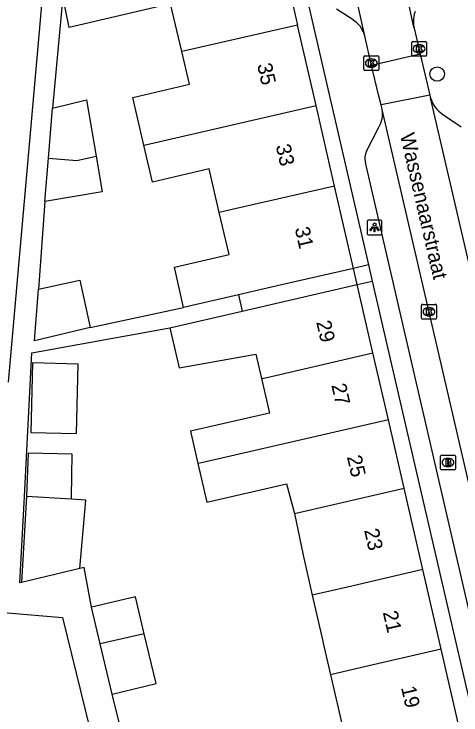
# Model space of a CAD drawing. Extents: x 160861 to 161308, y 384024 to 384878.
# Drawn here: x 160956.66 to 160986.91, y 384771.23 to 384818.67 of the extents above; entities that cross this region are included whole.
import ezdxf

# ---------------------------------------------------------------- set-up
doc = ezdxf.new("R2010")
doc.units = 0
for name, color, linetype in [('IMGEO_Boom', 7, 'Continuous'), ('IMGEO_Brandkraan', 7, 'Continuous'), ('IMGEO_Kolk', 7, 'Continuous'), ('IMGEO_Lichtpunt', 7, 'Continuous'), ('IMGEO_Openbare_ruimte_label', 7, 'Continuous'), ('IMGEO_Pand', 7, 'Continuous'), ('IMGEO_Pand_nummerreeks', 7, 'Continuous'), ('IMGEO_Pand_overbouw', 7, 'Continuous'), ('IMGEO_Rijbaan_lokaal_open', 7, 'Continuous'), ('IMGEO_Voetpad_open', 7, 'Continuous')]:
    doc.layers.add(name, color=color, linetype=linetype)

msp = doc.modelspace()

# ---------------------------------------------------------------- linework, layer by layer
at = {"layer": 'IMGEO_Boom'}
msp.add_circle((160985.295, 384814.604), 0.489, dxfattribs=at)
at = {"layer": 'IMGEO_Brandkraan'}
for p, q in [((160985.526, 384787.894), (160985.526, 384788.746)), ((160985.601, 384788.82), (160986.453, 384788.82)), ((160986.014, 384788.6), (160986.039, 384788.6)), ((160986.527, 384788.746), (160986.527, 384787.894)), ((160986.037, 384788.04), (160986.012, 384788.04)), ((160986.453, 384787.82), (160985.601, 384787.82))]:
    msp.add_line(p, q, dxfattribs=at)
for points in [[(160985.526, 384787.894), (160985.526, 384788.746)], [(160985.601, 384788.82), (160986.453, 384788.82)], [(160985.874, 384788.52), (160985.874, 384788.12), (160986.087, 384788.12)], [(160986.105, 384788.52), (160985.874, 384788.52)], [(160986.053, 384788.439), (160985.999, 384788.439), (160985.999, 384788.363)], [(160986.527, 384788.746), (160986.527, 384787.894)], [(160985.999, 384788.363), (160986.052, 384788.363)], [(160986.061, 384788.287), (160985.999, 384788.287), (160985.999, 384788.206)], [(160985.999, 384788.206), (160986.061, 384788.206)], [(160986.453, 384787.82), (160985.601, 384787.82)]]:
    msp.add_lwpolyline(points, dxfattribs=at)
for centre, radius, start, end in [((160985.603, 384788.744), 0.0765, 91.552, 178.448), ((160985.603, 384788.744), 0.0765, 91.552, 178.448), ((160986.054, 384788.401), 0.0379, 267.8285, 90.9355), ((160986.109, 384788.375), 0.145, 59.4692, 91.5367), ((160986.134, 384788.422), 0.0922, 285.5137, 58.1501), ((160986.451, 384788.744), 0.0765, 1.552, 88.448), ((160986.451, 384788.744), 0.0765, 1.552, 88.448), ((160986.062, 384788.246), 0.0404, 269.8759, 90.5077), ((160986.093, 384788.371), 0.251, 268.6676, 293.5347), ((160986.139, 384788.23), 0.105, 301.3115, 78.989), ((160985.603, 384787.896), 0.0765, 181.552, 268.448), ((160985.603, 384787.896), 0.0765, 181.552, 268.448), ((160986.451, 384787.896), 0.0765, 271.552, 358.448), ((160986.451, 384787.896), 0.0765, 271.552, 358.448)]:
    msp.add_arc(centre, radius, start, end, dxfattribs=at)
for centre, major_axis, ratio, start_param, end_param in [((160986.013, 384788.32), (-0.387, 0.002), 0.722429, 4.712389, 7.853982), ((160986.038, 384788.32), (-0.39, 0.002), 0.717154, 1.570796, 4.712389)]:
    msp.add_ellipse(centre, major_axis=major_axis, ratio=ratio, start_param=start_param, end_param=end_param, dxfattribs=at)
at = {"layer": 'IMGEO_Kolk'}
for p, q in [((160983.572, 384815.895), (160983.572, 384816.747)), ((160983.647, 384816.821), (160984.499, 384816.821)), ((160984.06, 384816.601), (160984.085, 384816.601)), ((160984.573, 384816.747), (160984.573, 384815.895)), ((160984.083, 384816.041), (160984.058, 384816.041)), ((160980.337, 384814.922), (160980.337, 384815.774)), ((160980.412, 384815.848), (160981.264, 384815.848)), ((160980.825, 384815.628), (160980.85, 384815.628)), ((160981.338, 384815.774), (160981.338, 384814.922)), ((160984.499, 384815.821), (160983.647, 384815.821)), ((160980.848, 384815.068), (160980.823, 384815.068)), ((160981.264, 384814.848), (160980.412, 384814.848)), ((160984.242, 384798.095), (160984.242, 384798.947)), ((160984.317, 384799.021), (160985.169, 384799.021)), ((160985.243, 384798.947), (160985.243, 384798.095)), ((160984.73, 384798.801), (160984.755, 384798.801)), ((160985.169, 384798.021), (160984.317, 384798.021)), ((160984.753, 384798.241), (160984.728, 384798.241))]:
    msp.add_line(p, q, dxfattribs=at)
for points in [[(160983.572, 384815.895), (160983.572, 384816.747)], [(160983.647, 384816.821), (160984.499, 384816.821)], [(160983.893, 384816.521), (160984.016, 384816.521), (160984.016, 384816.37), (160984.146, 384816.521), (160984.31, 384816.521), (160984.164, 384816.37), (160984.317, 384816.121), (160984.165, 384816.121), (160984.08, 384816.285), (160984.016, 384816.218), (160984.016, 384816.121), (160983.893, 384816.121), (160983.893, 384816.521)], [(160984.573, 384816.747), (160984.573, 384815.895)], [(160980.337, 384814.922), (160980.337, 384815.774)], [(160980.412, 384815.848), (160981.264, 384815.848)], [(160980.658, 384815.548), (160980.781, 384815.548), (160980.781, 384815.397), (160980.911, 384815.548), (160981.075, 384815.548), (160980.929, 384815.397), (160981.082, 384815.148), (160980.93, 384815.148), (160980.845, 384815.312), (160980.781, 384815.245), (160980.781, 384815.148), (160980.658, 384815.148), (160980.658, 384815.548)], [(160981.338, 384815.774), (160981.338, 384814.922)], [(160984.499, 384815.821), (160983.647, 384815.821)], [(160981.264, 384814.848), (160980.412, 384814.848)], [(160984.242, 384798.095), (160984.242, 384798.947)], [(160984.317, 384799.021), (160985.169, 384799.021)], [(160985.243, 384798.947), (160985.243, 384798.095)], [(160984.563, 384798.721), (160984.686, 384798.721), (160984.686, 384798.57), (160984.816, 384798.721), (160984.98, 384798.721), (160984.834, 384798.57), (160984.987, 384798.321), (160984.835, 384798.321), (160984.75, 384798.485), (160984.686, 384798.418), (160984.686, 384798.321), (160984.563, 384798.321), (160984.563, 384798.721)], [(160985.169, 384798.021), (160984.317, 384798.021)]]:
    msp.add_lwpolyline(points, dxfattribs=at)
for centre, start, end in [((160983.649, 384816.745), 91.552, 178.448), ((160983.649, 384816.745), 91.552, 178.448), ((160984.497, 384816.745), 1.552, 88.448), ((160984.497, 384816.745), 1.552, 88.448), ((160983.649, 384815.897), 181.552, 268.448), ((160983.649, 384815.897), 181.552, 268.448), ((160984.497, 384815.897), 271.552, 358.448), ((160984.497, 384815.897), 271.552, 358.448), ((160980.414, 384815.772), 91.552, 178.448), ((160980.414, 384815.772), 91.552, 178.448), ((160981.262, 384815.772), 1.552, 88.448), ((160981.262, 384815.772), 1.552, 88.448), ((160980.414, 384814.924), 181.552, 268.448), ((160980.414, 384814.924), 181.552, 268.448), ((160981.262, 384814.924), 271.552, 358.448), ((160981.262, 384814.924), 271.552, 358.448), ((160984.319, 384798.945), 91.552, 178.448), ((160984.319, 384798.945), 91.552, 178.448), ((160985.167, 384798.945), 1.552, 88.448), ((160985.167, 384798.945), 1.552, 88.448), ((160984.319, 384798.097), 181.552, 268.448), ((160984.319, 384798.097), 181.552, 268.448), ((160985.167, 384798.097), 271.552, 358.448), ((160985.167, 384798.097), 271.552, 358.448)]:
    msp.add_arc(centre, 0.0765, start, end, dxfattribs=at)
for centre, major_axis, ratio, start_param, end_param in [((160984.059, 384816.321), (-0.387, 0.002), 0.722429, 4.712389, 7.853982), ((160984.084, 384816.321), (-0.39, 0.002), 0.717154, 1.570796, 4.712389), ((160980.824, 384815.348), (-0.387, 0.002), 0.722429, 4.712389, 7.853982), ((160980.849, 384815.348), (-0.39, 0.002), 0.717154, 1.570796, 4.712389), ((160984.729, 384798.521), (-0.387, 0.002), 0.722429, 4.712389, 7.853982), ((160984.754, 384798.521), (-0.39, 0.002), 0.717154, 1.570796, 4.712389)]:
    msp.add_ellipse(centre, major_axis=major_axis, ratio=ratio, start_param=start_param, end_param=end_param, dxfattribs=at)
at = {"layer": 'IMGEO_Lichtpunt'}
for p, q in [((160980.559, 384804.63), (160980.559, 384803.823)), ((160980.559, 384804.63), (160980.559, 384803.823)), ((160981.461, 384804.725), (160980.653, 384804.725)), ((160981.461, 384804.725), (160980.653, 384804.725)), ((160981.555, 384803.823), (160981.555, 384804.63)), ((160981.555, 384803.823), (160981.555, 384804.63)), ((160980.653, 384803.729), (160981.461, 384803.729)), ((160980.653, 384803.729), (160981.461, 384803.729))]:
    msp.add_line(p, q, dxfattribs=at)
for points in [[(160980.933, 384804.294), (160980.972, 384804.266), (160980.784, 384804.004), (160980.746, 384804.031), (160980.933, 384804.294)], [(160981.035, 384804.246), (160981.082, 384804.246), (160981.082, 384803.924), (160981.035, 384803.924), (160981.035, 384804.246)], [(160981.145, 384804.266), (160981.183, 384804.293), (160981.37, 384804.031), (160981.331, 384804.003), (160981.145, 384804.266)]]:
    msp.add_lwpolyline(points, dxfattribs=at)
msp.add_circle((160981.058, 384804.428), 0.0994, dxfattribs=at)
for centre, start, end in [((160980.653, 384804.63), 90, 180), ((160980.653, 384804.63), 90, 180), ((160981.461, 384804.63), 0, 90), ((160981.461, 384804.63), 0, 90), ((160980.653, 384803.823), 180, 270), ((160980.653, 384803.823), 180, 270), ((160981.461, 384803.823), 270, 0), ((160981.461, 384803.823), 270, 360)]:
    msp.add_arc(centre, 0.0946, start, end, dxfattribs=at)
at = {"layer": 'IMGEO_Pand'}
for points in [[(160974.598, 384823.39), (160975.854, 384817.922)], [(160968.016, 384816.123), (160967.262, 384819.358), (160960.397, 384817.757), (160959.974, 384819.878)], [(160975.854, 384817.922), (160968.433, 384816.219), (160968.016, 384816.123)], [(160977.106, 384812.471), (160975.854, 384817.922)], [(160965.446, 384809.795), (160964.693, 384813.026), (160968.53, 384813.92), (160968.016, 384816.123)], [(160959.274, 384812.307), (160961.568, 384812.871), (160962.213, 384809.053)], [(160958.996, 384808.906), (160959.274, 384812.307)], [(160965.446, 384809.795), (160965.561, 384809.821), (160977.106, 384812.471)], [(160978.359, 384807.02), (160977.106, 384812.471)], [(160970.551, 384805.228), (160969.863, 384808.183), (160966.03, 384807.289), (160965.446, 384809.795)], [(160962.213, 384809.053), (160962.621, 384806.628), (160958.756, 384805.976)], [(160958.756, 384805.976), (160958.996, 384808.906)], [(160958.996, 384808.906), (160960.902, 384808.752), (160962.213, 384809.053)], [(160978.359, 384807.02), (160970.934, 384805.316), (160970.551, 384805.228)], [(160979.637, 384801.455), (160978.359, 384807.02)], [(160968.14, 384798.8), (160967.511, 384801.53), (160971.212, 384802.392), (160970.551, 384805.228)], [(160979.637, 384801.455), (160974.766, 384800.33), (160971.85, 384799.657), (160968.14, 384798.8)], [(160958.33, 384800.056), (160961.112, 384800.658), (160961.825, 384797.445)], [(160967.211, 384797.436), (160972.104, 384798.566), (160975.016, 384799.239), (160979.887, 384800.364)], [(160980.952, 384795.728), (160979.887, 384800.364)], [(160961.825, 384797.445), (160958.051, 384796.556), (160958.33, 384800.056)], [(160967.211, 384797.436), (160967.837, 384794.729), (160973.036, 384795.65), (160973.418, 384793.994)], [(160973.418, 384793.994), (160973.671, 384794.052), (160980.952, 384795.728)], [(160981.994, 384791.21), (160980.952, 384795.728)], [(160957.811, 384790.342), (160960.899, 384790.268), (160961.012, 384794.977), (160957.924, 384795.051), (160957.811, 384790.342)], [(160973.418, 384793.994), (160973.954, 384791.665), (160968.601, 384790.431), (160969.105, 384788.244)], [(160981.994, 384791.21), (160969.354, 384788.301), (160969.105, 384788.244)], [(160983.061, 384786.576), (160981.994, 384791.21)], [(160960.546, 384785.833), (160960.549, 384786.001), (160960.605, 384788.882), (160957.618, 384788.94), (160957.507, 384786.01)], [(160969.105, 384788.244), (160969.706, 384785.634), (160975.015, 384786.858), (160975.107, 384786.879), (160975.637, 384784.867)], [(160975.637, 384784.867), (160983.061, 384786.576)], [(160984.327, 384781.065), (160983.061, 384786.576)], [(160957.507, 384786.01), (160957.169, 384780.202)], [(160960.546, 384785.833), (160957.507, 384786.01)], [(160961.124, 384781.133), (160961.529, 384785.776), (160960.546, 384785.833)], [(160975.637, 384784.867), (160976.218, 384782.051), (160976.841, 384779.342)], [(160961.124, 384781.133), (160957.169, 384780.202)], [(160984.327, 384781.065), (160979.218, 384779.889), (160976.841, 384779.342)], [(160985.57, 384775.673), (160984.327, 384781.065)], [(160965.477, 384776.726), (160964.878, 384779.235), (160961.905, 384778.526)], [(160976.841, 384779.342), (160977.557, 384776.23), (160977.589, 384776.092), (160978.082, 384773.949)], [(160962.498, 384776.04), (160961.905, 384778.526)], [(160965.477, 384776.726), (160962.498, 384776.04)], [(160963.308, 384772.645), (160966.282, 384773.355), (160965.477, 384776.726)], [(160963.308, 384772.645), (160962.498, 384776.04)], [(160985.57, 384775.673), (160980.088, 384774.411), (160978.082, 384773.949)], [(160986.809, 384770.279), (160985.57, 384775.673)], [(160978.082, 384773.949), (160978.663, 384771.424), (160979.323, 384768.556)]]:
    msp.add_lwpolyline(points, dxfattribs=at)
at = {"layer": 'IMGEO_Pand_overbouw'}
msp.add_lwpolyline([(160972.104, 384798.566), (160975.016, 384799.239), (160979.887, 384800.364), (160979.637, 384801.455), (160974.766, 384800.33), (160971.85, 384799.657)], close=True, dxfattribs=at)
at = {"layer": 'IMGEO_Rijbaan_lokaal_open'}
for points in [[(160983.723, 384817.77), (160982.15, 384825.052), (160978.754, 384843.764), (160977.479, 384850.76), (160976.949, 384853.403)], [(160980.396, 384817.197), (160979.13, 384822.843), (160975.504, 384842.631)], [(160983.723, 384817.77), (160983.735, 384817.713), (160984.148, 384815.959)], [(160980.859, 384815.191), (160980.425, 384817.077), (160980.396, 384817.197)], [(160984.148, 384815.959), (160980.859, 384815.191)], [(160984.148, 384815.959), (160984.802, 384813.187)], [(160981.505, 384812.531), (160981.317, 384813.205), (160980.859, 384815.191)], [(160984.802, 384813.187), (160981.505, 384812.531)], [(160984.802, 384813.187), (160984.845, 384813.002)], [(160993.911, 384774.013), (160984.845, 384813.002)], [(160981.582, 384812.198), (160981.505, 384812.531)], [(160990.844, 384772.229), (160981.582, 384812.198)]]:
    msp.add_lwpolyline(points, dxfattribs=at)
at = {"layer": 'IMGEO_Voetpad_open'}
for points in [[(160970.553, 384852.358), (160975.639, 384823.391), (160980.654, 384801.69)], [(160959.326, 384823.509), (160958.656, 384823.569), (160958.566, 384819.819), (160956.275, 384793.744)], [(160959.974, 384819.878), (160959.274, 384812.307)], [(160979.533, 384818.317), (160978.474, 384819.007)], [(160983.801, 384818.843), (160983.748, 384818.67), (160983.711, 384818.492), (160983.689, 384818.312), (160983.684, 384818.131), (160983.695, 384817.949), (160983.723, 384817.77)], [(160984.845, 384813.002), (160984.902, 384812.832), (160984.974, 384812.667), (160985.06, 384812.51), (160985.16, 384812.361), (160985.273, 384812.221), (160985.398, 384812.092), (160985.534, 384811.975), (160985.592, 384811.931), (160986.863, 384811.084), (160986.93, 384811.038)], [(160980.523, 384809.39), (160981.346, 384811.011)], [(160989.414, 384769.78), (160980.441, 384808.622)], [(160958.756, 384805.976), (160958.33, 384800.056)], [(160980.654, 384801.69), (160979.637, 384801.455)], [(160980.654, 384801.69), (160980.906, 384800.6)], [(160979.887, 384800.364), (160980.906, 384800.6)], [(160980.906, 384800.6), (160992.6, 384750), (160996.597, 384732.705), (160996.604, 384732.664)], [(160961.825, 384797.445), (160968.14, 384798.8)], [(160957.169, 384780.202), (160957.05, 384780.174), (160957.365, 384786.01), (160957.866, 384795.73), (160967.211, 384797.436)], [(160961.905, 384778.526), (160961.401, 384781.198), (160961.124, 384781.133)], [(160955.398, 384778.213), (160959.946, 384777.823), (160963.919, 384761.651)], [(160964.601, 384767.849), (160964.488, 384767.822), (160963.308, 384772.645)]]:
    msp.add_lwpolyline(points, dxfattribs=at)
for centre, radius, start, end in [((160978.585, 384816.694), 1.88, 15.5236, 59.7075), ((160979.751, 384811.945), 1.848, 329.6407, 7.8694), ((160981.484, 384808.899), 1.079, 152.9419, 194.8693)]:
    msp.add_arc(centre, radius, start, end, dxfattribs=at)

# ---------------------------------------------------------------- texts
at = {"layer": 'IMGEO_Openbare_ruimte_label'}
msp.add_text('Wassenaarstraat', height=1, rotation=283.0633, dxfattribs=at).set_placement((160982.772, 384810.49))
at = {"layer": 'IMGEO_Pand_nummerreeks'}
for s, rotation, p in [('35', 282.9377, (160973.105, 384815.235)), ('33', 282.9377, (160974.365, 384809.751)), ('31', 282.9377, (160975.651, 384804.158)), ('29', 282.9622, (160977.106, 384797.82)), ('27', 282.9622, (160978.126, 384793.555)), ('25', 282.9601, (160979.181, 384788.698)), ('23', 282.9601, (160980.347, 384783.731)), ('21', 282.9601, (160981.612, 384778.172)), ('19', 282.9601, (160982.848, 384773.078))]:
    msp.add_text(s, height=1, rotation=rotation, dxfattribs=at).set_placement(p)

doc.saveas('drawing.dxf')
